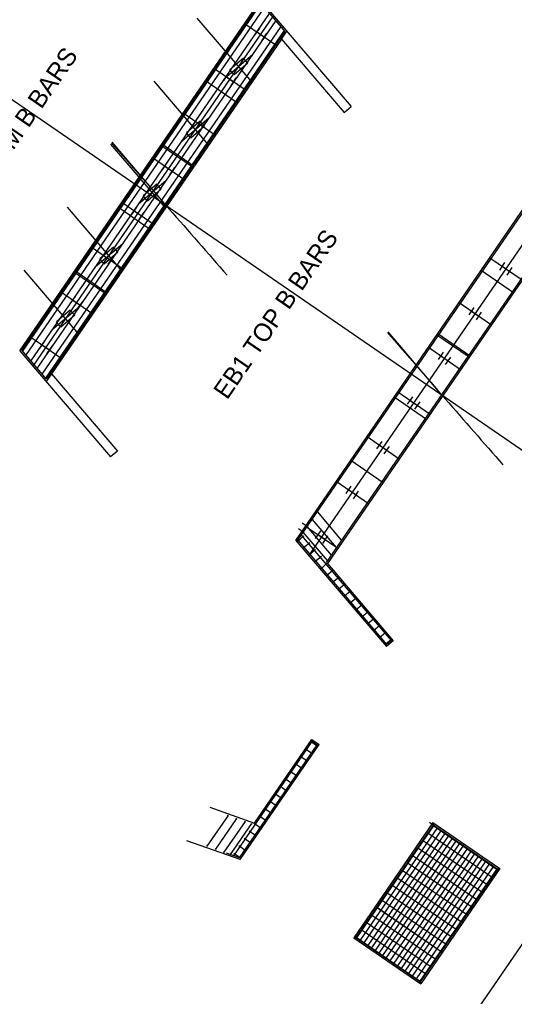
# Model space of a CAD drawing. Extents: x 2378999 to 2381348, y 331302 to 333122.
# Drawn here: x 2379360.9 to 2379415.6, y 331652.7 to 331760.8 of the extents above; entities that cross this region are included whole.
import ezdxf

# ---------------------------------------------------------------- set-up
doc = ezdxf.new("R2010")
doc.units = 0
for name, color, linetype in [('Arrowhead Terminators', 7, 'Continuous'), ('Dimension Lines', 7, 'Continuous'), ('Dimension Lines CELL', 7, 'Continuous'), ('Mis Work Point CELL', 7, 'Continuous'), ('P_SMU_Bent_Cap', 7, 'Continuous'), ('P_SMU_D_Deck_Outline', 7, 'Continuous'), ('P_SMU_Girder_Concrete', 7, 'Continuous'), ('P_SMU_Mis_L_Lines', 7, 'Continuous'), ('P_SMU_Mis_Long_Chord', 7, 'Continuous'), ('P_SMU_Rebar_B_Bar', 7, 'Continuous'), ('P_SMU_Rebar_H_Bar', 7, 'Continuous'), ('P_SMU_Rebar_U_Bar', 7, 'Continuous'), ('P_SMU_Rebar_V_Bar', 7, 'Continuous'), ('Plan Sheet CELL', 7, 'Continuous'), ('Rebar Lines', 7, 'Continuous'), ('Scratch_Level_0', 7, 'Continuous'), ('Sup Concrete Slab Lines', 7, 'Continuous'), ('Text', 7, 'Continuous')]:
    doc.layers.add(name, color=color, linetype=linetype)

msp = doc.modelspace()

# ---------------------------------------------------------------- linework, layer by layer
at = {"layer": 'Arrowhead Terminators'}
for p, q in [((2379361.17, 331724.08), (2379387.59, 331762.54)), ((2379361.55, 331723.64), (2379387.97, 331762.1)), ((2379362.11, 331722.99), (2379388.53, 331761.44)), ((2379389.2, 331760.66), (2379362.78, 331722.2)), ((2379389.76, 331760), (2379363.34, 331721.55)), ((2379390.14, 331759.56), (2379363.72, 331721.11))]:
    msp.add_line(p, q, dxfattribs=at)
at = {"layer": 'Dimension Lines'}
for p, q in [((2379392.25, 331704.09), (2379391.72, 331704.46)), ((2379392.68, 331704.71), (2379392.15, 331705.08)), ((2379383.47, 331668.68), (2379383.42, 331668.53)), ((2379384.18, 331668.43), (2379384.12, 331668.28))]:
    msp.add_line(p, q, dxfattribs=at)
at = {"layer": 'Dimension Lines CELL'}
msp.add_line((2379454.16, 331687.23), (2379268.2, 331815), dxfattribs=at)
at = {"layer": 'Mis Work Point CELL'}
for p, q in [((2379362.35, 331722.45), (2379388.96, 331761.19)), ((2379402.05, 331637.52), (2379479.08, 331749.64)), ((2379392.88, 331701.47), (2379419.5, 331740.21))]:
    msp.add_line(p, q, dxfattribs=at)
at = {"layer": 'P_SMU_Bent_Cap'}
for p, q in [((2379386.63, 331756.88), (2379383.59, 331754.28)), ((2379381.84, 331749.91), (2379378.8, 331747.31)), ((2379377.05, 331742.94), (2379374.01, 331740.35)), ((2379372.27, 331735.97), (2379369.23, 331733.38)), ((2379367.48, 331729.01), (2379364.44, 331726.41))]:
    msp.add_line(p, q, dxfattribs=at)
at = {"layer": 'P_SMU_D_Deck_Outline'}
for p, q in [((2379385.63, 331756.52), (2379384.11, 331755.22)), ((2379386.11, 331755.95), (2379385.63, 331756.52)), ((2379384.59, 331754.65), (2379384.11, 331755.22)), ((2379386.11, 331755.95), (2379384.59, 331754.65)), ((2379380.84, 331749.55), (2379379.32, 331748.25)), ((2379381.33, 331748.98), (2379379.8, 331747.68)), ((2379381.33, 331748.98), (2379380.84, 331749.55)), ((2379379.8, 331747.68), (2379379.32, 331748.25)), ((2379376.05, 331742.58), (2379374.53, 331741.28)), ((2379376.54, 331742.01), (2379376.05, 331742.58)), ((2379375.02, 331740.71), (2379374.53, 331741.28)), ((2379376.54, 331742.01), (2379375.02, 331740.71)), ((2379371.26, 331735.61), (2379369.74, 331734.31)), ((2379371.75, 331735.04), (2379370.23, 331733.74)), ((2379371.75, 331735.04), (2379371.26, 331735.61)), ((2379370.23, 331733.74), (2379369.74, 331734.31)), ((2379366.47, 331728.64), (2379364.95, 331727.34)), ((2379366.96, 331728.07), (2379366.47, 331728.64)), ((2379365.44, 331726.77), (2379364.95, 331727.34)), ((2379366.96, 331728.07), (2379365.44, 331726.77))]:
    msp.add_line(p, q, dxfattribs=at)
at = {"layer": 'P_SMU_Girder_Concrete'}
for p, q in [((2379386.86, 331759), (2379387.43, 331759.82)), ((2379387.14, 331759.41), (2379387.95, 331758.85)), ((2379387.67, 331758.44), (2379388.24, 331759.26)), ((2379383.46, 331754.05), (2379384.03, 331754.88)), ((2379383.74, 331754.46), (2379384.55, 331753.91)), ((2379384.27, 331753.49), (2379384.84, 331754.32)), ((2379380.06, 331749.11), (2379380.63, 331749.93)), ((2379380.35, 331749.52), (2379381.16, 331748.96)), ((2379380.87, 331748.55), (2379381.44, 331749.37)), ((2379376.67, 331744.16), (2379377.23, 331744.99)), ((2379376.95, 331744.57), (2379377.76, 331744.02)), ((2379377.48, 331743.6), (2379378.04, 331744.43)), ((2379373.27, 331739.22), (2379373.83, 331740.04)), ((2379373.55, 331739.63), (2379374.36, 331739.07)), ((2379374.08, 331738.66), (2379374.65, 331739.48)), ((2379369.87, 331734.27), (2379370.44, 331735.09)), ((2379370.15, 331734.68), (2379370.96, 331734.13)), ((2379370.68, 331733.71), (2379371.25, 331734.54)), ((2379414, 331733.07), (2379414.56, 331733.9)), ((2379414.28, 331733.49), (2379415.09, 331732.93)), ((2379414.81, 331732.52), (2379415.37, 331733.34)), ((2379366.47, 331729.33), (2379367.04, 331730.15)), ((2379366.76, 331729.74), (2379367.57, 331729.18)), ((2379367.28, 331728.77), (2379367.85, 331729.59)), ((2379410.6, 331728.13), (2379411.16, 331728.95)), ((2379410.88, 331728.54), (2379411.69, 331727.98)), ((2379411.41, 331727.57), (2379411.98, 331728.4)), ((2379363.08, 331724.38), (2379363.64, 331725.2)), ((2379363.36, 331724.79), (2379364.17, 331724.24)), ((2379363.89, 331723.82), (2379364.45, 331724.65)), ((2379407.2, 331723.18), (2379407.77, 331724.01)), ((2379407.48, 331723.59), (2379408.29, 331723.04)), ((2379408.01, 331722.63), (2379408.58, 331723.45)), ((2379403.8, 331718.24), (2379404.37, 331719.06)), ((2379404.09, 331718.65), (2379404.9, 331718.09)), ((2379404.61, 331717.68), (2379405.18, 331718.5)), ((2379400.41, 331713.29), (2379400.97, 331714.12)), ((2379400.69, 331713.7), (2379401.5, 331713.15)), ((2379401.22, 331712.74), (2379401.78, 331713.56)), ((2379397.01, 331708.35), (2379397.57, 331709.17)), ((2379397.29, 331708.76), (2379398.1, 331708.2)), ((2379397.82, 331707.79), (2379398.38, 331708.61)), ((2379393.61, 331703.4), (2379394.18, 331704.23)), ((2379393.89, 331703.81), (2379394.7, 331703.26)), ((2379394.42, 331702.84), (2379394.99, 331703.67))]:
    msp.add_line(p, q, dxfattribs=at)
at = {"layer": 'P_SMU_Mis_L_Lines'}
for p, q in [((2379386.57, 331753.88), (2379380.53, 331760.94)), ((2379381.78, 331746.91), (2379375.75, 331753.97)), ((2379376.99, 331739.94), (2379370.96, 331747)), ((2379372.2, 331732.97), (2379366.17, 331740.03)), ((2379367.42, 331726), (2379361.38, 331733.06))]:
    msp.add_line(p, q, dxfattribs=at)
at = {"layer": 'P_SMU_Mis_Long_Chord'}
for centre in [(2384709.4, 336397.77), (2384739.93, 336376.79)]:
    msp.add_arc(centre, 7080, 221.06156, 221.218654, dxfattribs=at)
at = {"layer": 'P_SMU_Rebar_B_Bar'}
for p, q in [((2379360.89, 331724.16), (2379387.51, 331762.9)), ((2379387.51, 331762.9), (2379397.54, 331751.15)), ((2379389.83, 331758.63), (2379390.42, 331759.49)), ((2379389.83, 331758.63), (2379364.39, 331721.6)), ((2379389.83, 331758.63), (2379396.78, 331750.5)), ((2379381.42, 331754.04), (2379384.99, 331751.58)), ((2379396.78, 331750.5), (2379397.54, 331751.15)), ((2379376.61, 331747.03), (2379380.18, 331744.58)), ((2379391.43, 331703.18), (2379418.04, 331741.92)), ((2379371.79, 331740.02), (2379375.36, 331737.57)), ((2379420.37, 331737.65), (2379394.93, 331700.62)), ((2379366.98, 331733.02), (2379370.55, 331730.56)), ((2379411.95, 331733.06), (2379415.52, 331730.6)), ((2379407.14, 331726.05), (2379410.71, 331723.6)), ((2379360.89, 331724.16), (2379370.93, 331712.41)), ((2379364.39, 331721.6), (2379363.81, 331720.75)), ((2379364.39, 331721.6), (2379371.69, 331713.06)), ((2379402.33, 331719.05), (2379405.9, 331716.59)), ((2379371.69, 331713.06), (2379370.93, 331712.41)), ((2379397.51, 331712.04), (2379401.08, 331709.59)), ((2379391.43, 331703.18), (2379401.46, 331691.43)), ((2379394.93, 331700.62), (2379402.22, 331692.08)), ((2379402.22, 331692.08), (2379401.46, 331691.43)), ((2379385.27, 331667.87), (2379394.02, 331680.6)), ((2379386.84, 331671.91), (2379393.2, 331681.17)), ((2379393.2, 331681.17), (2379394.02, 331680.6)), ((2379381.9, 331673.66), (2379386.84, 331671.91)), ((2379406.59, 331671.97), (2379397.84, 331659.23)), ((2379406.59, 331671.97), (2379414, 331666.88)), ((2379385.27, 331667.87), (2379379.36, 331669.96)), ((2379410.07, 331669.58), (2379401.32, 331656.85)), ((2379414, 331666.88), (2379405.25, 331654.14)), ((2379400.23, 331662.71), (2379407.64, 331657.62)), ((2379397.84, 331659.23), (2379405.25, 331654.14))]:
    msp.add_line(p, q, dxfattribs=at)
at = {"layer": 'P_SMU_Rebar_H_Bar'}
for p, q in [((2379392.03, 331703.76), (2379392.5, 331704.45)), ((2379391.64, 331703.19), (2379392.11, 331703.88)), ((2379392.03, 331703.76), (2379401.99, 331692.1)), ((2379391.64, 331703.19), (2379401.48, 331691.67)), ((2379384.56, 331668.3), (2379393.24, 331680.94)), ((2379385.21, 331668.07), (2379393.79, 331680.56)), ((2379406.7, 331671.69), (2379398.14, 331659.23)), ((2379407.11, 331671.41), (2379398.55, 331658.95)), ((2379407.53, 331671.12), (2379398.97, 331658.66)), ((2379407.94, 331670.84), (2379399.38, 331658.38)), ((2379408.35, 331670.56), (2379399.79, 331658.1)), ((2379408.76, 331670.27), (2379400.2, 331657.81)), ((2379409.18, 331669.99), (2379400.61, 331657.53)), ((2379409.59, 331669.71), (2379401.03, 331657.25)), ((2379410.41, 331669.15), (2379401.85, 331656.69)), ((2379410.82, 331668.86), (2379402.26, 331656.4)), ((2379384.56, 331668.3), (2379383.77, 331668.58)), ((2379385.21, 331668.07), (2379384.42, 331668.35)), ((2379411.23, 331668.58), (2379402.67, 331656.12)), ((2379411.64, 331668.3), (2379403.08, 331655.84)), ((2379412.05, 331668.01), (2379403.49, 331655.55)), ((2379412.47, 331667.73), (2379403.91, 331655.27)), ((2379412.88, 331667.45), (2379404.32, 331654.99)), ((2379413.29, 331667.16), (2379404.73, 331654.7)), ((2379413.7, 331666.88), (2379405.14, 331654.42))]:
    msp.add_line(p, q, dxfattribs=at)
at = {"layer": 'P_SMU_Rebar_U_Bar'}
for p, q in [((2379395.94, 331702.39), (2379393.25, 331705.53)), ((2379396.5, 331703.21), (2379393.81, 331706.36)), ((2379395.37, 331701.56), (2379392.68, 331704.71)), ((2379394.94, 331700.94), (2379392.25, 331704.09)), ((2379383.93, 331672.76), (2379381.59, 331669.35)), ((2379384.87, 331672.43), (2379382.53, 331669.02)), ((2379385.82, 331672.1), (2379383.47, 331668.68)), ((2379386.52, 331671.85), (2379384.18, 331668.43))]:
    msp.add_line(p, q, dxfattribs=at)
at = {"layer": 'P_SMU_Rebar_V_Bar'}
for p, q in [((2379406.59, 331671.67), (2379413.72, 331666.76)), ((2379405.45, 331670.02), (2379412.59, 331665.12)), ((2379406.02, 331670.84), (2379413.16, 331665.94)), ((2379404.89, 331669.2), (2379412.03, 331664.29)), ((2379404.32, 331668.37), (2379411.46, 331663.47)), ((2379403.19, 331666.72), (2379410.33, 331661.82)), ((2379403.76, 331667.55), (2379410.89, 331662.64)), ((2379402.62, 331665.9), (2379409.76, 331661)), ((2379402.06, 331665.08), (2379409.19, 331660.17)), ((2379400.92, 331663.43), (2379408.06, 331658.52)), ((2379401.49, 331664.25), (2379408.63, 331659.35)), ((2379400.36, 331662.6), (2379407.5, 331657.7)), ((2379399.79, 331661.78), (2379406.93, 331656.87)), ((2379398.66, 331660.13), (2379405.8, 331655.23)), ((2379399.23, 331660.95), (2379406.36, 331656.05)), ((2379398.09, 331659.31), (2379405.23, 331654.4))]:
    msp.add_line(p, q, dxfattribs=at)
for centre in [(2379393.26, 331705.52), (2379393.82, 331706.34), (2379392.69, 331704.69), (2379392.27, 331704.08), (2379391.7, 331703.15), (2379392.35, 331702.39), (2379395.92, 331702.4), (2379396.49, 331703.23), (2379393, 331701.63), (2379395.36, 331701.58), (2379393.65, 331700.87), (2379394.3, 331700.11), (2379394.93, 331700.96), (2379394.95, 331699.35), (2379395.42, 331699.75), (2379396.07, 331698.99), (2379395.6, 331698.59), (2379396.72, 331698.23), (2379396.25, 331697.83), (2379396.9, 331697.07), (2379397.37, 331697.47), (2379397.54, 331696.31), (2379398.02, 331696.71), (2379398.67, 331695.95), (2379398.19, 331695.55), (2379398.84, 331694.79), (2379399.32, 331695.19), (2379399.49, 331694.03), (2379399.97, 331694.43), (2379400.62, 331693.67), (2379400.14, 331693.27), (2379400.79, 331692.5), (2379401.27, 331692.91), (2379401.44, 331691.74), (2379401.92, 331692.15), (2379393.21, 331680.86), (2379392.65, 331680.03), (2379393.16, 331679.68), (2379393.73, 331680.5), (2379392.08, 331679.21), (2379392.59, 331678.86), (2379390.95, 331677.56), (2379391.51, 331678.39), (2379392.03, 331678.03), (2379390.38, 331676.74), (2379390.9, 331676.38), (2379391.46, 331677.21), (2379389.81, 331675.91), (2379390.33, 331675.56), (2379388.68, 331674.26), (2379389.25, 331675.09), (2379389.76, 331674.73), (2379388.12, 331673.44), (2379388.63, 331673.09), (2379389.2, 331673.91), (2379383.92, 331672.75), (2379384.86, 331672.41), (2379385.8, 331672.08), (2379387.55, 331672.62), (2379388.06, 331672.26), (2379386.51, 331671.83), (2379386.98, 331671.79), (2379387.5, 331671.44), (2379386.37, 331669.79), (2379386.93, 331670.61), (2379381.6, 331669.37), (2379382.54, 331669.03), (2379383.48, 331668.7), (2379385.8, 331668.97), (2379384.19, 331668.45), (2379385.23, 331668.14)]:
    msp.add_circle(centre, 0.0208, dxfattribs=at)
at = {"layer": 'Plan Sheet CELL'}
for p, q in [((2379377.14, 331740.15), (2379371.11, 331747.21)), ((2379407.67, 331719.17), (2379401.64, 331726.23))]:
    msp.add_line(p, q, dxfattribs=at)
at = {"layer": 'Rebar Lines'}
for p, q in [((2379385.76, 331760.36), (2379389.33, 331757.9)), ((2379382.36, 331755.41), (2379385.94, 331752.96)), ((2379378.97, 331750.47), (2379382.54, 331748.01)), ((2379375.57, 331745.52), (2379379.14, 331743.07)), ((2379372.17, 331740.58), (2379375.74, 331738.12)), ((2379368.77, 331735.63), (2379372.35, 331733.18)), ((2379412.9, 331734.43), (2379416.47, 331731.98)), ((2379365.38, 331730.69), (2379368.95, 331728.23)), ((2379409.5, 331729.49), (2379413.07, 331727.03)), ((2379361.98, 331725.74), (2379365.55, 331723.29)), ((2379406.1, 331724.54), (2379409.67, 331722.09)), ((2379402.71, 331719.6), (2379406.28, 331717.14)), ((2379399.31, 331714.65), (2379402.88, 331712.2)), ((2379395.91, 331709.71), (2379399.48, 331707.25)), ((2379392.51, 331704.76), (2379396.08, 331702.31))]:
    msp.add_line(p, q, dxfattribs=at)
at = {"layer": 'Scratch_Level_0'}
for p, q in [((2379361.1, 331724.17), (2379387.52, 331762.62)), ((2379387.52, 331762.62), (2379390.21, 331759.47)), ((2379390.21, 331759.47), (2379363.79, 331721.02)), ((2379376.51, 331746.89), (2379380.08, 331744.44)), ((2379391.56, 331703.09), (2379418.18, 331741.82)), ((2379420.23, 331737.75), (2379394.79, 331700.72)), ((2379366.88, 331732.88), (2379370.46, 331730.43)), ((2379407.05, 331725.91), (2379410.62, 331723.46)), ((2379361.1, 331724.17), (2379363.79, 331721.02)), ((2379392.32, 331703.68), (2379391.56, 331703.03)), ((2379392.97, 331702.92), (2379392.21, 331702.27)), ((2379393.62, 331702.16), (2379392.86, 331701.51)), ((2379394.27, 331701.4), (2379393.5, 331700.75)), ((2379394.91, 331700.64), (2379394.15, 331699.99)), ((2379395.56, 331699.88), (2379394.8, 331699.23)), ((2379396.21, 331699.11), (2379395.45, 331698.47)), ((2379396.86, 331698.35), (2379396.1, 331697.71)), ((2379397.51, 331697.59), (2379396.75, 331696.94)), ((2379398.16, 331696.83), (2379397.4, 331696.18)), ((2379398.81, 331696.07), (2379398.05, 331695.42)), ((2379399.46, 331695.31), (2379398.7, 331694.66)), ((2379400.11, 331694.55), (2379399.35, 331693.9)), ((2379400.76, 331693.79), (2379400, 331693.14)), ((2379401.41, 331693.03), (2379400.65, 331692.38)), ((2379402.06, 331692.27), (2379401.3, 331691.62)), ((2379402.11, 331692.21), (2379401.35, 331691.56)), ((2379393.06, 331680.96), (2379393.88, 331680.4)), ((2379393.1, 331681.03), (2379393.93, 331680.47)), ((2379392.49, 331680.14), (2379393.31, 331679.57)), ((2379391.36, 331678.49), (2379392.18, 331677.93)), ((2379391.92, 331679.32), (2379392.75, 331678.75)), ((2379390.79, 331677.67), (2379391.62, 331677.1)), ((2379390.23, 331676.84), (2379391.05, 331676.28)), ((2379389.66, 331676.02), (2379390.48, 331675.45)), ((2379388.53, 331674.37), (2379389.35, 331673.8)), ((2379389.09, 331675.19), (2379389.92, 331674.63)), ((2379387.96, 331673.55), (2379388.78, 331672.98)), ((2379387.39, 331672.72), (2379388.22, 331672.16)), ((2379406.22, 331672.02), (2379413.91, 331666.74)), ((2379386.26, 331671.07), (2379387.09, 331670.51)), ((2379386.83, 331671.9), (2379387.65, 331671.33)), ((2379406.73, 331671.88), (2379397.98, 331659.14)), ((2379385.7, 331670.25), (2379386.52, 331669.68)), ((2379385.13, 331669.43), (2379385.95, 331668.86)), ((2379384.56, 331668.6), (2379385.39, 331668.03)), ((2379413.87, 331666.97), (2379405.12, 331654.24)), ((2379397.94, 331659.37), (2379405.35, 331654.28))]:
    msp.add_line(p, q, dxfattribs=at)
at = {"layer": 'Text'}
for p, q in [((2379375.67, 331741.84), (2379375.67, 331741.84)), ((2379406.2, 331720.86), (2379406.2, 331720.86))]:
    msp.add_line(p, q, dxfattribs=at)

# ---------------------------------------------------------------- texts
at = {"layer": 'Sup Concrete Slab Lines'}
for s, p in [('EB1 BOTTOM B BARS', (2379351.66, 331733.89)), ('EB1 TOP B BARS', (2379383.83, 331718.65))]:
    msp.add_text(s, height=2, rotation=55.5093, dxfattribs=at).set_placement(p)

doc.saveas('drawing.dxf')
